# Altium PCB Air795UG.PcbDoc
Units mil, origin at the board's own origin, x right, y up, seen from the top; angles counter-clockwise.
Board outline 6000 x 4000 mil, 2 copper layers (Top, Bottom), stack 12.7 mil thick; 1 components, 0 nets, 126 pads, 0 vias.
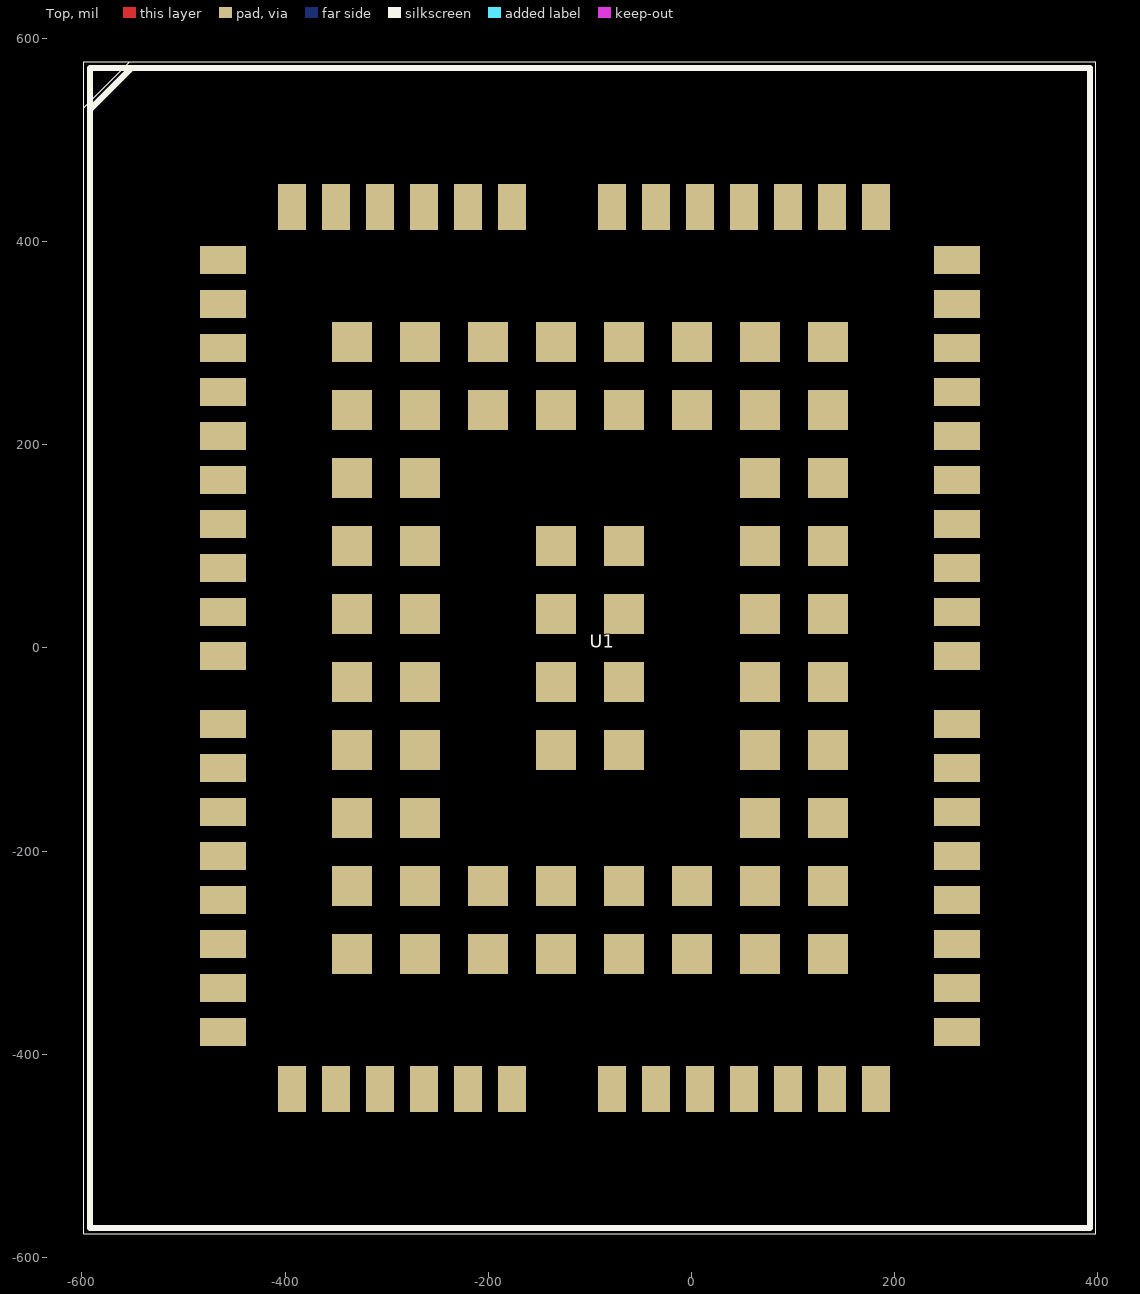
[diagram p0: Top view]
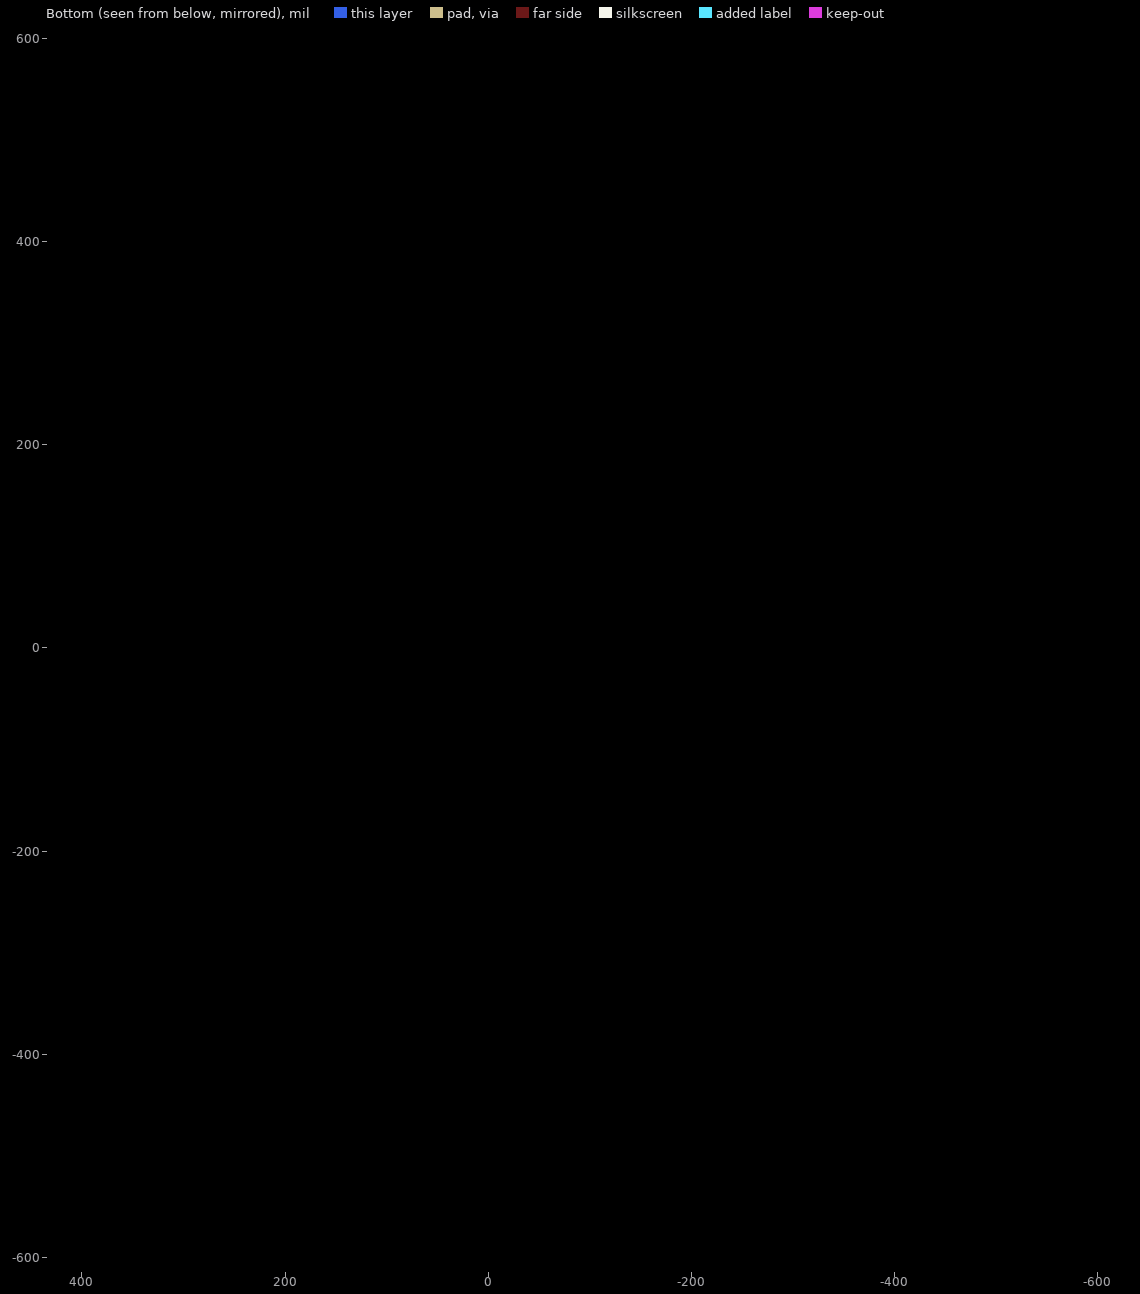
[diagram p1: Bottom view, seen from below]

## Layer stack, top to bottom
Top: signal copper 1.35
Dielectric: dielectric 10, FR-4, Dk 4.3
Bottom: signal copper 1.35

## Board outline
-9000,-9000 -3000,-9000 -3000,-5000 -9000,-5000

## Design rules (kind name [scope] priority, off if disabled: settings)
Clearance [All] p1: gap=10
PolygonConnect [All] p1: connectstyle=Relief reliefconductorwidth=10 reliefentries=4 polygonreliefangle="90 Angle" airgapwidth=10
RoutingVias [All] p1: holewidth=28 width=50 viastyle="Through Hole" minholewidth=28 minwidth=50 maxholewidth=28 maxwidth=50
SolderMaskExpansion [All] p1: expansion=4
Width [All] p1: maxlimit=10 minlimit=10 preferedwidth=10
28 further rules are at their usual default settings.

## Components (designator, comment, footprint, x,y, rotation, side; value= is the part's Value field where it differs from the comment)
U1 "AIR795U-GL" AIR795U-GL -100,0 r0 top

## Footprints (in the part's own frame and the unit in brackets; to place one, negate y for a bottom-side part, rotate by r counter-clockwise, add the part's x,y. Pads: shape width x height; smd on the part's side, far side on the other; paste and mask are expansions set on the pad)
AIR795U-GL [mm]
  rect 1.15x0.7 smd mask+0.05: 1(-9.175,9.7) 2(-9.175,8.6) 3(-9.175,7.5) 4(-9.175,6.4) 5(-9.175,5.3) 6(-9.175,4.2) 7(-9.175,3.1) 8(-9.175,2) 9(-9.175,0.9) 10(-9.175,-0.2) 11(-9.175,-1.9) 12(-9.175,-3) 13(-9.175,-4.1) 14(-9.175,-5.2) 15(-9.175,-6.3) 16(-9.175,-7.4) 17(-9.175,-8.5) 18(-9.175,-9.6) 32(9.175,-9.6) 33(9.175,-8.5) 34(9.175,-7.4) 35(9.175,-6.3) 36(9.175,-5.2) 37(9.175,-4.1) 38(9.175,-3) 39(9.175,-1.9) 40(9.175,-0.2) 41(9.175,0.9) 42(9.175,2) 43(9.175,3.1) 44(9.175,4.2) 45(9.175,5.3) 46(9.175,6.4) 47(9.175,7.5) 48(9.175,8.6) 49(9.175,9.7)
  rect 0.7x1.15 smd mask+0.05: 19(-7.45,-11.025) 20(-6.35,-11.025) 21(-5.25,-11.025) 22(-4.15,-11.025) 23(-3.05,-11.025) 24(-1.95,-11.025) 25(0.55,-11.025) 26(1.65,-11.025) 27(2.75,-11.025) 28(3.85,-11.025) 29(4.95,-11.025) 30(6.05,-11.025) 31(7.15,-11.025) 50(7.15,11.025) 51(6.05,11.025) 52(4.95,11.025) 53(3.85,11.025) 54(2.75,11.025) 55(1.65,11.025) 56(0.55,11.025) 57(-1.95,11.025) 58(-3.05,11.025) 59(-4.15,11.025) 60(-5.25,11.025) 61(-6.35,11.025) 62(-7.45,11.025)
  rect 1x1 smd mask+0.05: 63(-5.95,4.25) 64(-5.95,2.55) 65(-5.95,0.85) 66(-5.95,-0.85) 67(-5.95,-2.55) 68(-5.95,-4.25) 69(-2.55,-7.65) 70(-0.85,-7.65) 71(0.85,-7.65) 72(2.55,-7.65) 73(5.95,-4.25) 74(5.95,-2.55) 75(5.95,-0.85) 76(5.95,0.85) 77(5.95,2.55) 78(5.95,4.25) 79(2.55,7.65) 80(0.85,7.65) 81(-0.85,7.65) 82(-2.55,7.65) 83(-4.25,4.25) 84(-4.25,2.55) 85(-4.25,0.85) 86(-4.25,-0.85) 87(-4.25,-2.55) 88(-4.25,-4.25) 89(-2.55,-5.95) 90(-0.85,-5.95) 91(0.85,-5.95) 92(2.55,-5.95) 93(4.25,-4.25) 94(4.25,-2.55) 95(4.25,-0.85) 96(4.25,0.85) 97(4.25,2.55) 98(4.25,4.25) 99(2.55,5.95) 100(0.85,5.95) 101(-0.85,5.95) 102(-2.55,5.95) 103(-5.95,7.65) 104(-5.95,5.95) 105(-5.95,-5.95) 106(-5.95,-7.65) 107(-4.25,-7.65) 108(4.25,-7.65) 109(5.95,-7.65) 110(5.95,-5.95) 111(5.95,5.95) 112(5.95,7.65) 113(4.25,7.65) 114(-4.25,7.65) 115(-4.25,5.95) 116(-4.25,-5.95) 117(4.25,-5.95) 118(4.25,5.95) 119(-0.85,2.55) 120(-0.85,0.85) 121(-0.85,-0.85) 122(-0.85,-2.55) 123(0.85,-2.55) 124(0.85,-0.85) 125(0.85,0.85) 126(0.85,2.55)
  silkscreen extent -12.65,-14.65 12.65,14.65

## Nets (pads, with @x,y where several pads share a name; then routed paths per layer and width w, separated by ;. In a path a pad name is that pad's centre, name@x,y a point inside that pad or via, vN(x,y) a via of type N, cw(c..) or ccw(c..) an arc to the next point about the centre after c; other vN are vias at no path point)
pads on no net: U1.1 U1.2 U1.3 U1.4 U1.5 U1.6 U1.7 U1.8 U1.9 U1.10 U1.11 U1.12 U1.13 U1.14 U1.15 U1.16 U1.17 U1.18 U1.19 U1.20 U1.21 U1.22 U1.23 U1.24 U1.25 U1.26 U1.27 U1.28 U1.29 U1.30 U1.31 U1.32 U1.33 U1.34 U1.35 U1.36 U1.37 U1.38 U1.39 U1.40 U1.41 U1.42 U1.43 U1.44 U1.45 U1.46 U1.47 U1.48 U1.49 U1.50 U1.51 U1.52 U1.53 U1.54 U1.55 U1.56 U1.57 U1.58 U1.59 U1.60 U1.61 U1.62 U1.63 U1.64 U1.65 U1.66 U1.67 U1.68 U1.69 U1.70 U1.71 U1.72 U1.73 U1.74 U1.75 U1.76 U1.77 U1.78 U1.79 U1.80 U1.81 U1.82 U1.83 U1.84 U1.85 U1.86 U1.87 U1.88 U1.89 U1.90 U1.91 U1.92 U1.93 U1.94 U1.95 U1.96 U1.97 U1.98 U1.99 U1.100 U1.101 U1.102 U1.103 U1.104 U1.105 U1.106 U1.107 U1.108 U1.109 U1.110 U1.111 U1.112 U1.113 U1.114 U1.115 U1.116 U1.117 U1.118 U1.119 U1.120 U1.121 U1.122 U1.123 U1.124 U1.125 U1.126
